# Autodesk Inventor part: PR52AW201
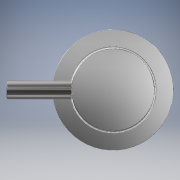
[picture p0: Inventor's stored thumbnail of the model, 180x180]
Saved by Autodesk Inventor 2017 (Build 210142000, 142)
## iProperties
Created: 2021-04
Part Number: PR52AW201
Material: Generico
Document SubType Name: Modeling
Designer: PIZZERA
Density: 1 g/cm^3
Appearance: Default
Author: PIZZERA
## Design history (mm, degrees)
feature "Base3"
node "Solido3"
node "Solido5"
